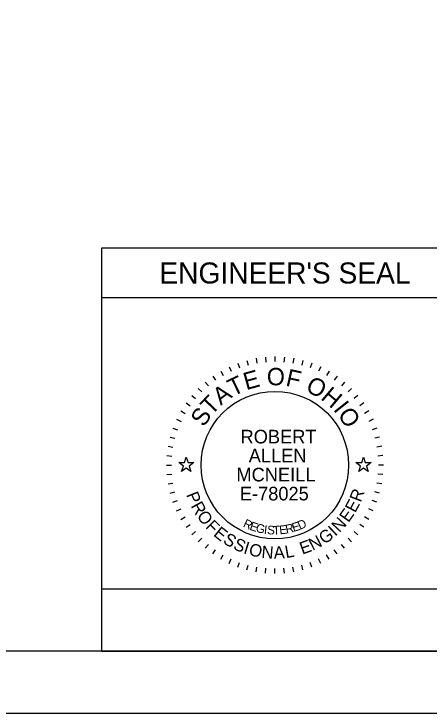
# Model space of a CAD drawing. Extents: x 0 to 34, y 0 to 22.
# Drawn here: x 6.64 to 9.99, y 0 to 5.64 of the extents above; entities that cross this region are included whole.
import ezdxf

# ---------------------------------------------------------------- set-up
doc = ezdxf.new("R2010")
doc.units = 0
for name, color, linetype in [('SH_Border', 7, 'Continuous'), ('SH_Cut_Line', 7, 'Continuous'), ('SH_Data', 7, 'Continuous'), ('SH_Seal', 7, 'Continuous')]:
    doc.layers.add(name, color=color, linetype=linetype)

msp = doc.modelspace()

# ---------------------------------------------------------------- linework, layer by layer
at = {"layer": 'SH_Border'}
msp.add_lwpolyline([(1.5, 21.5), (33.5, 21.5), (33.5, 0.5), (1.5, 0.5)], close=True, dxfattribs=at)
at = {"layer": 'SH_Cut_Line'}
msp.add_lwpolyline([(0, 0), (34, 0), (34, 22), (0, 22)], close=True, dxfattribs=at)
at = {"layer": 'SH_Data'}
for p, q in [((10.15, 3.75), (7.35, 3.75)), ((7.35, 3.75), (7.35, 0.5)), ((10.15, 3.35), (7.35, 3.35)), ((10.15, 0.5), (7.35, 0.5))]:
    msp.add_line(p, q, dxfattribs=at)
msp.add_lwpolyline([(10.15, 0.5), (10.15, 1), (7.35, 1), (7.35, 0.5)], close=True, dxfattribs=at)
at = {"layer": 'SH_Seal'}
for p, q in [((8.4507, 2.8222), (8.4644, 2.7846)), ((8.5235, 2.8452), (8.5339, 2.8065)), ((8.5981, 2.8617), (8.605, 2.8223)), ((8.6737, 2.8717), (8.6772, 2.8318)), ((8.75, 2.875), (8.75, 2.835)), ((8.8263, 2.8717), (8.8228, 2.8318)), ((8.9019, 2.8617), (8.895, 2.8223)), ((8.9765, 2.8452), (8.9661, 2.8065)), ((9.0493, 2.8222), (9.0356, 2.7846)), ((8.3802, 2.793), (8.3971, 2.7568)), ((9.1198, 2.793), (9.1029, 2.7568)), ((8.2481, 2.7168), (8.2711, 2.684)), ((8.3125, 2.7578), (8.3325, 2.7231)), ((9.1875, 2.7578), (9.1675, 2.7231)), ((9.2519, 2.7168), (9.2289, 2.684)), ((8.1876, 2.6703), (8.2133, 2.6396)), ((9.3124, 2.6703), (9.2867, 2.6396)), ((8.1313, 2.6187), (8.1596, 2.5904)), ((9.3687, 2.6187), (9.3404, 2.5904)), ((8.0797, 2.5624), (8.1104, 2.5367)), ((9.4203, 2.5624), (9.3896, 2.5367)), ((8.0332, 2.5019), (8.066, 2.4789)), ((9.4668, 2.5019), (9.434, 2.4789)), ((7.9922, 2.4375), (8.0269, 2.4175)), ((9.5078, 2.4375), (9.4731, 2.4175)), ((7.957, 2.3698), (7.9932, 2.3529)), ((9.543, 2.3698), (9.5068, 2.3529)), ((7.9278, 2.2993), (7.9654, 2.2856)), ((9.5722, 2.2993), (9.5346, 2.2856)), ((7.9048, 2.2265), (7.9435, 2.2161)), ((9.5952, 2.2265), (9.5565, 2.2161)), ((7.8883, 2.1519), (7.9277, 2.145)), ((9.6117, 2.1519), (9.5723, 2.145)), ((7.8783, 2.0763), (7.9182, 2.0728)), ((9.6217, 2.0763), (9.5818, 2.0728)), ((7.875, 2), (7.915, 2)), ((9.625, 2), (9.585, 2)), ((7.8783, 1.9237), (7.9182, 1.9272)), ((9.6217, 1.9237), (9.5818, 1.9272)), ((7.8883, 1.8481), (7.9277, 1.855)), ((9.6117, 1.8481), (9.5723, 1.855)), ((7.9048, 1.7735), (7.9435, 1.7839)), ((9.5952, 1.7735), (9.5565, 1.7839)), ((7.9278, 1.7007), (7.9654, 1.7144)), ((9.5722, 1.7007), (9.5346, 1.7144)), ((7.957, 1.6302), (7.9932, 1.6471)), ((9.543, 1.6302), (9.5068, 1.6471)), ((7.9922, 1.5625), (8.0269, 1.5825)), ((9.5078, 1.5625), (9.4731, 1.5825)), ((8.0332, 1.4981), (8.066, 1.5211)), ((9.4668, 1.4981), (9.434, 1.5211)), ((8.0797, 1.4376), (8.1104, 1.4633)), ((9.4203, 1.4376), (9.3896, 1.4633)), ((8.1313, 1.3813), (8.1596, 1.4096)), ((8.1876, 1.3297), (8.2133, 1.3604)), ((9.3124, 1.3297), (9.2867, 1.3604)), ((9.3687, 1.3813), (9.3404, 1.4096)), ((8.2481, 1.2832), (8.2711, 1.316)), ((9.2519, 1.2832), (9.2289, 1.316)), ((8.3125, 1.2422), (8.3325, 1.2769)), ((8.3802, 1.207), (8.3971, 1.2432)), ((9.1198, 1.207), (9.1029, 1.2432)), ((9.1875, 1.2422), (9.1675, 1.2769)), ((8.4507, 1.1778), (8.4644, 1.2154)), ((8.5235, 1.1548), (8.5339, 1.1935)), ((8.9765, 1.1548), (8.9661, 1.1935)), ((9.0493, 1.1778), (9.0356, 1.2154)), ((8.5981, 1.1383), (8.605, 1.1777)), ((8.6737, 1.1283), (8.6772, 1.1682)), ((8.75, 1.125), (8.75, 1.165)), ((8.8263, 1.1283), (8.8228, 1.1682)), ((8.9019, 1.1383), (8.895, 1.1777))]:
    msp.add_line(p, q, dxfattribs=at)
for points in [[(7.9736, 2.02), (8.0205, 2.02), (8.035, 2.0645), (8.0495, 2.02), (8.0964, 2.02), (8.0585, 1.9924), (8.073, 1.9478), (8.035, 1.9754), (7.997, 1.9478), (8.0115, 1.9924)], [(9.4036, 2.02), (9.4505, 2.02), (9.465, 2.0645), (9.4795, 2.02), (9.5264, 2.02), (9.4885, 1.9924), (9.503, 1.9478), (9.465, 1.9754), (9.427, 1.9478), (9.4415, 1.9924)]]:
    msp.add_lwpolyline(points, close=True, dxfattribs=at)
msp.add_circle((8.75, 2), 0.595, dxfattribs=at)

# ---------------------------------------------------------------- texts
at = {"layer": 'SH_Data'}
msp.add_text("ENGINEER'S SEAL", height=0.17, dxfattribs=at).set_placement((7.8176, 3.465))
at = {"layer": 'SH_Seal'}
for s, height, rotation, p in [('E', 0.14, 15.7571, (8.5184, 2.6038)), ('O', 0.14, 359.7812, (8.6847, 2.6443)), ('F', 0.14, 347.4362, (8.8311, 2.6417)), ('T', 0.14, 25.7167, (8.4116, 2.5518)), ('O', 0.14, 332.2586, (8.9898, 2.6015)), ('A', 0.14, 36.4747, (8.3134, 2.4781)), ('H', 0.14, 319.9136, (9.1132, 2.5361)), ('T', 0.14, 46.4344, (8.2383, 2.3964)), ('I', 0.14, 308.367, (9.2165, 2.4483)), ('S', 0.14, 57.1924, (8.1781, 2.3014)), ('O', 0.14, 303.1491, (9.2521, 2.4089)), ('R', 0.1, 69.2322, (9.4419, 1.6954)), ('P', 0.1, 291.494, (8.0323, 1.7621)), ('R', 0.1, 298.7311, (8.069, 1.6717)), ('E', 0.1, 61.9951, (9.3976, 1.6098)), ('E', 0.1, 54.758, (9.3433, 1.5314)), ('O', 0.1, 306.4666, (8.1155, 1.5883)), ('N', 0.1, 47.0224, (9.2702, 1.4508)), ('F', 0.1, 314.7068, (8.1843, 1.4983)), ('R', 0.07, 334.487, (8.4875, 1.5051)), ('E', 0.07, 341.04, (8.5406, 1.4801)), ('G', 0.07, 347.4752, (8.5914, 1.4618)), ('R', 0.07, 11.9184, (8.8425, 1.4474)), ('E', 0.07, 17.6836, (8.8998, 1.4602)), ('D', 0.07, 23.3052, (8.951, 1.477)), ('E', 0.1, 321.4393, (8.2478, 1.4348)), ('I', 0.07, 353.7858, (8.6591, 1.4468)), ('S', 0.07, 356.8926, (8.6858, 1.4429)), ('T', 0.07, 3.0061, (8.7357, 1.4387)), ('E', 0.07, 6.0117, (8.7889, 1.4412)), ('G', 0.1, 35.0469, (9.1481, 1.357)), ('I', 0.1, 43.287, (9.2368, 1.4214)), ('S', 0.1, 328.6764, (8.3243, 1.3752)), ('N', 0.1, 27.3113, (9.0545, 1.3075)), ('S', 0.1, 335.9134, (8.4064, 1.3266)), ('I', 0.1, 343.1505, (8.4906, 1.2897)), ('O', 0.1, 346.8859, (8.5339, 1.2751)), ('E', 0.1, 20.0742, (8.9712, 1.277)), ('N', 0.1, 355.1261, (8.6388, 1.2517)), ('A', 0.1, 2.8617, (8.7423, 1.2437)), ('L', 0.1, 10.0987, (8.8394, 1.249))]:
    msp.add_text(s, height=height, rotation=rotation, dxfattribs=at).set_placement(p)
for s, p in [('ROBERT', (8.4728, 2.1749)), ('ALLEN', (8.5389, 2.0216)), ('MCNEILL', (8.4398, 1.8684)), ('E-78025', (8.4673, 1.7151))]:
    msp.add_text(s, height=0.11, dxfattribs=at).set_placement(p)

doc.saveas('drawing.dxf')
